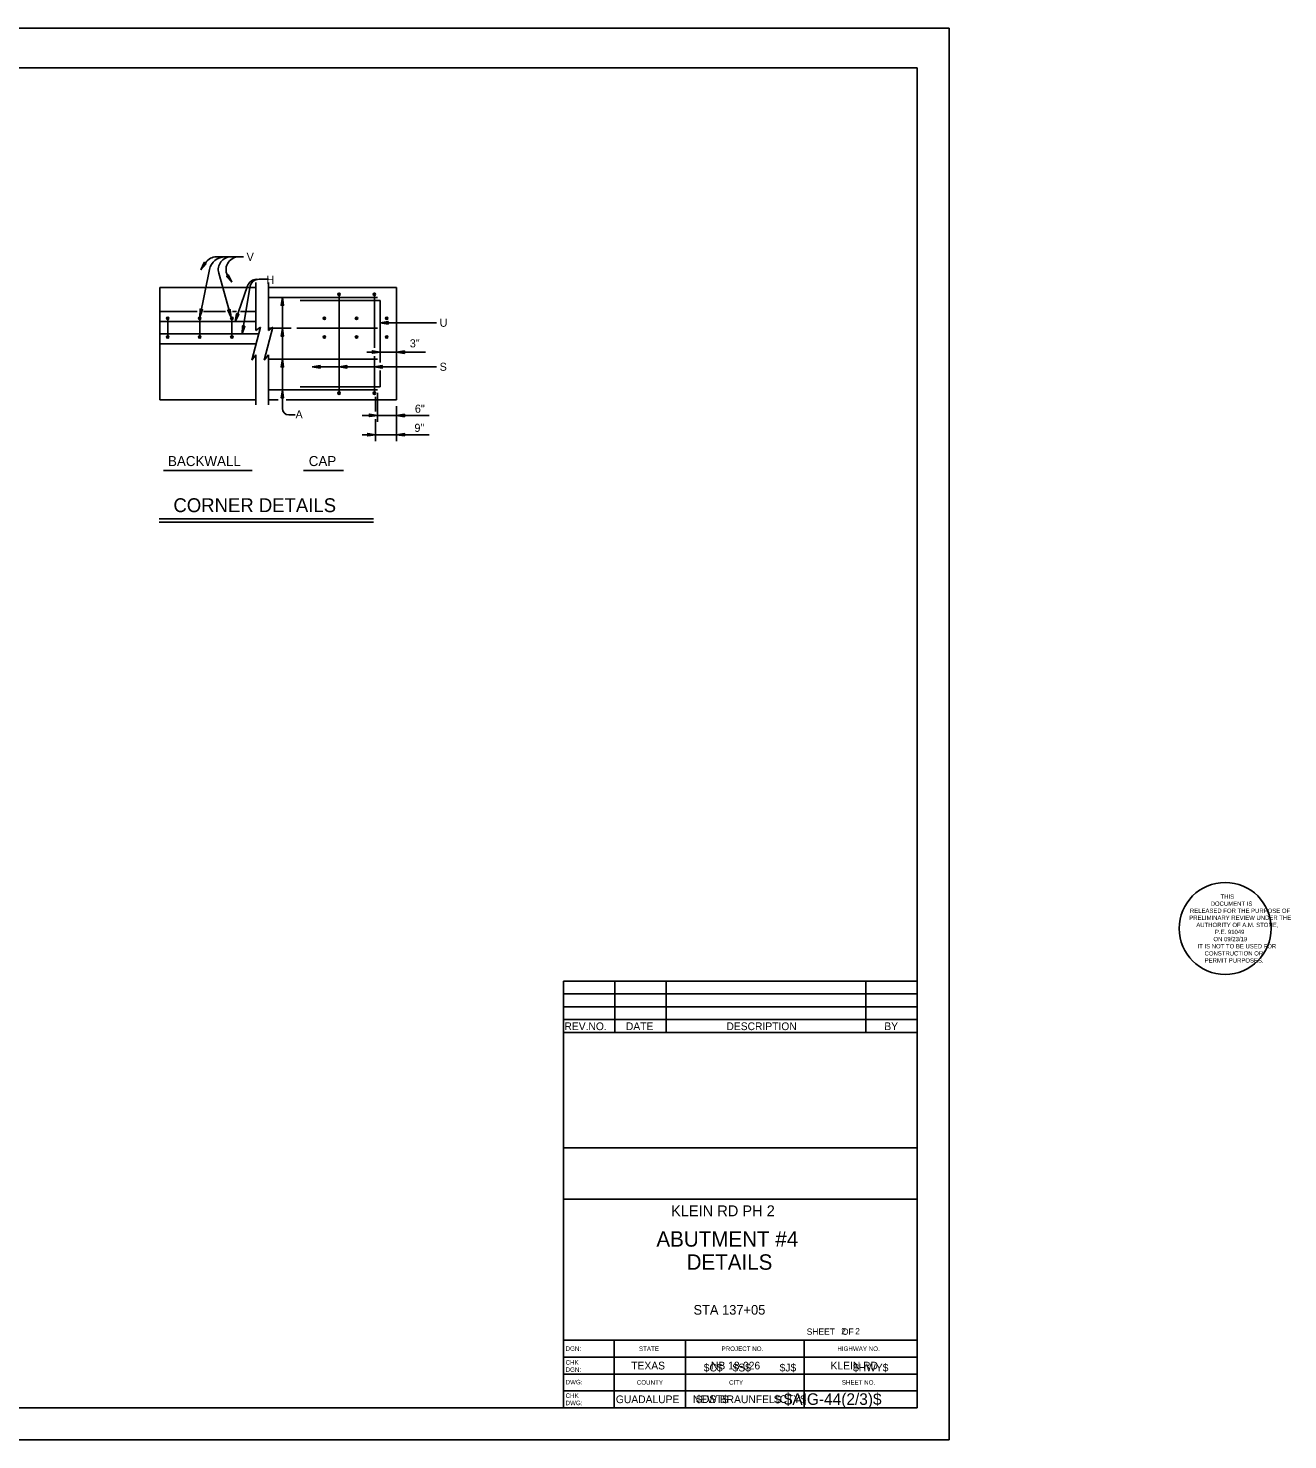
# Model space of a CAD drawing. Extents: x 926 to 1074, y 990 to 1081.
# Drawn here: x 1054.64 to 1074.28, y 1000 to 1022 of the extents above; entities that cross this region are included whole.
import ezdxf

# ---------------------------------------------------------------- set-up
doc = ezdxf.new("R2010")
doc.units = 0
for name, color, linetype in [('BORD_lines_major', 7, 'Continuous'), ('BORD_lines_minor', 7, 'Continuous'), ('BORD_text_large_1', 7, 'Continuous'), ('BORD_text_large_2', 7, 'Continuous'), ('BORD_text_small_1', 7, 'Continuous'), ('BORD_text_small_3', 7, 'Continuous'), ('BORD_text_small_proj', 7, 'Continuous'), ('C-MS-ANNO-TTLB-STMP', 7, 'Continuous'), ('D_BATCH_PLOT', 7, 'Continuous'), ('D_SHEET', 7, 'Continuous'), ('D_SHEET_NUM_CODE', 7, 'Continuous'), ('D_SHEET_TXT_SUB_CODE', 7, 'Continuous'), ('Working Level 1', 7, 'Continuous')]:
    doc.layers.add(name, color=color, linetype=linetype)

msp = doc.modelspace()

# ---------------------------------------------------------------- linework, layer by layer
at = {"layer": 'BORD_lines_major'}
for p, q in [((1037.413, 1021.382), (1068.5, 1021.382)), ((1068.5, 1000.5), (1068.5, 1021.382)), ((1037.413, 1000.5), (1068.5, 1000.5))]:
    msp.add_line(p, q, dxfattribs=at)
at = {"layer": 'BORD_lines_minor'}
for p, q in [((1062.988, 1007.15), (1068.5, 1007.15)), ((1062.988, 1006.35), (1062.988, 1007.15)), ((1062.988, 1006.95), (1068.5, 1006.95)), ((1063.788, 1007.15), (1063.788, 1006.35)), ((1064.588, 1007.15), (1064.588, 1006.35)), ((1067.7, 1006.35), (1067.7, 1007.15)), ((1062.988, 1006.75), (1068.5, 1006.75)), ((1062.988, 1006.55), (1068.5, 1006.55)), ((1062.988, 1006.35), (1068.5, 1006.35)), ((1062.988, 1006.35), (1062.988, 1004.55)), ((1062.988, 1004.55), (1068.5, 1004.55)), ((1062.988, 1004.55), (1062.988, 1000.5)), ((1062.988, 1003.75), (1068.5, 1003.75)), ((1062.988, 1001.55), (1068.5, 1001.55)), ((1063.776, 1001.55), (1063.776, 1000.5)), ((1064.888, 1001.55), (1064.888, 1000.5)), ((1066.738, 1001.55), (1066.738, 1000.5)), ((1062.988, 1001.287), (1068.5, 1001.287)), ((1062.988, 1001.025), (1068.5, 1001.025)), ((1062.988, 1000.762), (1068.5, 1000.762))]:
    msp.add_line(p, q, dxfattribs=at)
at = {"layer": 'C-MS-ANNO-TTLB-STMP'}
msp.add_circle((1073.305, 1007.969), 0.717, dxfattribs=at)
at = {"layer": 'D_BATCH_PLOT'}
msp.add_lwpolyline([(1035, 1000), (1069, 1000), (1069, 1022), (1035, 1022)], close=True, dxfattribs=at)
at = {"layer": 'D_SHEET'}
for p, q in [((1035, 1022), (1069, 1022)), ((1069, 1000), (1069, 1022)), ((1035, 1000), (1069, 1000))]:
    msp.add_line(p, q, dxfattribs=at)
at = {"layer": 'Working Level 1'}
for p, q in [((1057.574, 1018.437), (1057.995, 1018.437)), ((1057.315, 1017.498), (1057.466, 1018.237)), ((1057.33, 1018.236), (1057.409, 1018.35)), ((1057.611, 1018.184), (1057.803, 1017.492)), ((1056.692, 1016.208), (1056.692, 1017.958)), ((1058.192, 1017.958), (1056.692, 1017.958)), ((1057.818, 1018.041), (1057.761, 1018.124)), ((1057.867, 1017.429), (1058.062, 1017.987)), ((1057.979, 1017.237), (1058.094, 1017.961)), ((1058.192, 1017.288), (1058.192, 1018.036)), ((1058.388, 1018.087), (1058.242, 1018.087)), ((1058.385, 1017.288), (1058.385, 1018.036)), ((1058.385, 1017.958), (1060.385, 1017.958)), ((1060.385, 1016.208), (1060.385, 1017.958)), ((1058.385, 1017.804), (1060.085, 1017.804)), ((1058.604, 1016.074), (1058.604, 1017.804)), ((1058.881, 1017.754), (1060.131, 1017.754)), ((1059.487, 1017.854), (1059.487, 1016.312)), ((1060.039, 1017.854), (1060.039, 1017.018)), ((1060.131, 1017.754), (1060.131, 1016.789)), ((1057.276, 1017.583), (1056.692, 1017.583)), ((1057.718, 1017.583), (1057.374, 1017.583)), ((1057.891, 1017.583), (1057.826, 1017.583)), ((1058.192, 1017.583), (1057.949, 1017.583)), ((1058.192, 1017.429), (1056.692, 1017.429)), ((1056.817, 1017.187), (1056.817, 1017.479)), ((1057.317, 1017.187), (1057.317, 1017.479)), ((1057.817, 1017.187), (1057.817, 1017.479)), ((1058.126, 1016.827), (1058.264, 1017.34)), ((1058.264, 1017.34), (1058.192, 1017.288)), ((1058.319, 1016.827), (1058.457, 1017.34)), ((1058.457, 1017.34), (1058.385, 1017.288)), ((1058.385, 1017.324), (1058.435, 1017.324)), ((1058.453, 1017.324), (1058.74, 1017.324)), ((1058.829, 1017.324), (1060.085, 1017.324)), ((1060.131, 1017.41), (1061.009, 1017.41)), ((1058.237, 1017.237), (1056.692, 1017.237)), ((1058.195, 1017.083), (1056.692, 1017.083)), ((1058.192, 1016.907), (1058.126, 1016.827)), ((1058.192, 1016.13), (1058.192, 1016.907)), ((1058.385, 1016.907), (1058.319, 1016.827)), ((1058.385, 1016.13), (1058.385, 1016.907)), ((1058.385, 1016.843), (1060.085, 1016.843)), ((1060.835, 1016.952), (1059.92, 1016.952)), ((1060.039, 1016.89), (1060.039, 1016.312)), ((1059.068, 1016.724), (1061.009, 1016.724)), ((1060.131, 1016.665), (1060.131, 1016.412)), ((1058.881, 1016.412), (1060.131, 1016.412)), ((1058.192, 1016.208), (1056.692, 1016.208)), ((1058.385, 1016.362), (1060.085, 1016.362)), ((1058.385, 1016.208), (1058.539, 1016.208)), ((1058.663, 1016.208), (1060.385, 1016.208)), ((1060.058, 1016.253), (1060.058, 1016.026)), ((1060.085, 1016.315), (1060.085, 1015.865)), ((1058.704, 1015.974), (1058.803, 1015.974)), ((1060.892, 1015.965), (1059.848, 1015.965)), ((1060.385, 1016.108), (1060.385, 1015.565)), ((1060.058, 1015.909), (1060.058, 1015.565)), ((1060.892, 1015.665), (1059.848, 1015.665)), ((1056.751, 1015.108), (1058.135, 1015.108)), ((1058.933, 1015.108), (1059.555, 1015.108)), ((1056.681, 1014.353), (1060.025, 1014.353)), ((1056.681, 1014.303), (1060.025, 1014.303))]:
    msp.add_line(p, q, dxfattribs=at)
for points in [[(1057.33, 1018.236), (1057.383, 1018.349), (1057.415, 1018.327)], [(1057.818, 1018.041), (1057.765, 1018.153), (1057.733, 1018.131)], [(1058.604, 1017.804), (1058.584, 1017.682), (1058.623, 1017.682)], [(1057.315, 1017.498), (1057.359, 1017.614), (1057.321, 1017.622)], [(1057.803, 1017.492), (1057.79, 1017.616), (1057.752, 1017.605)], [(1057.867, 1017.429), (1057.926, 1017.538), (1057.89, 1017.551)], [(1057.979, 1017.237), (1058.018, 1017.355), (1057.98, 1017.361)], [(1058.604, 1017.324), (1058.584, 1017.201), (1058.623, 1017.201)], [(1060.131, 1017.41), (1060.253, 1017.39), (1060.253, 1017.428)], [(1058.604, 1016.843), (1058.584, 1016.72), (1058.623, 1016.72)], [(1060.131, 1016.952), (1060.008, 1016.972), (1060.008, 1016.934)], [(1060.385, 1016.952), (1060.507, 1016.932), (1060.507, 1016.971)], [(1059.068, 1016.724), (1059.191, 1016.704), (1059.191, 1016.742)], [(1059.487, 1016.724), (1059.609, 1016.704), (1059.609, 1016.742)], [(1060.039, 1016.724), (1060.162, 1016.704), (1060.162, 1016.742)], [(1058.604, 1016.362), (1058.584, 1016.24), (1058.623, 1016.24)], [(1060.085, 1015.965), (1059.962, 1015.985), (1059.962, 1015.946)], [(1060.385, 1015.965), (1060.507, 1015.945), (1060.507, 1015.984)], [(1060.058, 1015.665), (1059.935, 1015.685), (1059.935, 1015.646)], [(1060.385, 1015.665), (1060.507, 1015.645), (1060.507, 1015.684)]]:
    msp.add_lwpolyline(points, close=True, dxfattribs=at)
for centre, radius in [((1059.487, 1017.854), 0.0187), ((1059.487, 1017.854), 0.0117), ((1059.487, 1017.854), 0.00469), ((1060.039, 1017.854), 0.0187), ((1060.039, 1017.854), 0.0117), ((1060.039, 1017.854), 0.00469), ((1056.816, 1017.479), 0.0187), ((1056.816, 1017.479), 0.0117), ((1056.816, 1017.479), 0.00469), ((1057.316, 1017.479), 0.0187), ((1057.316, 1017.479), 0.0117), ((1057.316, 1017.479), 0.00469), ((1057.816, 1017.479), 0.0187), ((1057.816, 1017.479), 0.0117), ((1057.816, 1017.479), 0.00469), ((1059.26, 1017.479), 0.0187), ((1059.26, 1017.479), 0.0117), ((1059.26, 1017.479), 0.00469), ((1059.76, 1017.479), 0.0187), ((1059.76, 1017.479), 0.0117), ((1059.76, 1017.479), 0.00469), ((1060.231, 1017.479), 0.0187), ((1060.231, 1017.479), 0.0117), ((1060.231, 1017.479), 0.00469), ((1056.816, 1017.187), 0.0187), ((1056.816, 1017.187), 0.0117), ((1056.816, 1017.187), 0.00469), ((1057.316, 1017.187), 0.0187), ((1057.316, 1017.187), 0.0117), ((1057.316, 1017.187), 0.00469), ((1057.816, 1017.187), 0.0187), ((1057.816, 1017.187), 0.0117), ((1057.816, 1017.187), 0.00469), ((1059.26, 1017.187), 0.0187), ((1059.26, 1017.187), 0.0117), ((1059.26, 1017.187), 0.00469), ((1059.76, 1017.187), 0.0187), ((1059.76, 1017.187), 0.0117), ((1059.76, 1017.187), 0.00469), ((1060.231, 1017.187), 0.0187), ((1060.231, 1017.187), 0.0187), ((1060.231, 1017.187), 0.0117), ((1060.231, 1017.187), 0.0117), ((1060.231, 1017.187), 0.00469), ((1060.231, 1017.187), 0.00469), ((1059.487, 1016.312), 0.0187), ((1059.487, 1016.312), 0.0117), ((1059.487, 1016.312), 0.00469), ((1060.039, 1016.312), 0.0187), ((1060.039, 1016.312), 0.0117), ((1060.039, 1016.312), 0.00469)]:
    msp.add_circle(centre, radius, dxfattribs=at)
for centre, radius, start, end in [((1057.574, 1018.237), 0.2, 90, 145.4917), ((1057.711, 1018.187), 0.25, 90, 168.4552), ((1057.804, 1018.237), 0.2, 90, 195.5006), ((1057.925, 1018.237), 0.2, 90, 214.524), ((1058.203, 1017.937), 0.15, 90, 160.7438), ((1058.242, 1017.937), 0.15, 90, 170.9957), ((1058.704, 1016.074), 0.1, 180, 270)]:
    msp.add_arc(centre, radius, start, end, dxfattribs=at)

# ---------------------------------------------------------------- texts
at = {"layer": 'BORD_lines_minor'}
for s, p in [('REV.NO.', (1063.002, 1006.385)), ('DATE', (1063.96, 1006.385)), ('DESCRIPTION', (1065.528, 1006.385)), ('BY', (1067.99, 1006.385))]:
    msp.add_text(s, height=0.12, rotation=359.9834, dxfattribs=at).set_placement(p)
msp.add_text('KLEIN RD PH 2', height=0.17, dxfattribs=at).set_placement((1064.665, 1003.483))
at = {"layer": 'BORD_text_large_1'}
for s, p in [('ABUTMENT #4', (1064.436, 1003.01)), ('DETAILS', (1064.907, 1002.65))]:
    msp.add_text(s, height=0.24, dxfattribs=at).set_placement(p)
at = {"layer": 'BORD_text_large_2'}
msp.add_text('STA 137+05', height=0.15, dxfattribs=at).set_placement((1065.014, 1001.95))
at = {"layer": 'BORD_text_small_1'}
msp.add_text('SHEET   OF', height=0.0984, dxfattribs=at).set_placement((1066.78, 1001.636))
at = {"layer": 'BORD_text_small_3'}
msp.add_text('2    2', height=0.0984, dxfattribs=at).set_placement((1067.316, 1001.642))
at = {"layer": 'BORD_text_small_proj'}
for s, height, p in [('DGN:', 0.07, (1063.02, 1001.386)), ('STATE', 0.07, (1064.164, 1001.384)), ('PROJECT NO.', 0.07, (1065.452, 1001.384)), ('HIGHWAY NO.', 0.07, (1067.258, 1001.384)), ('CHK', 0.07, (1063.02, 1001.171)), ('DGN:', 0.07, (1063.02, 1001.058)), ('TEXAS', 0.12, (1064.044, 1001.096)), ('KLEIN RD', 0.12, (1067.151, 1001.096)), ('DWG:', 0.07, (1063.02, 1000.864)), ('COUNTY', 0.07, (1064.13, 1000.859)), ('CITY', 0.07, (1065.569, 1000.859)), ('SHEET NO.', 0.07, (1067.327, 1000.859)), ('CHK', 0.07, (1063.02, 1000.653)), ('DWG:', 0.07, (1063.02, 1000.539)), ('GUADALUPE', 0.12, (1063.804, 1000.571)), ('NEW BRAUNFELS', 0.12, (1065.005, 1000.571))]:
    msp.add_text(s, height=height, rotation=359.9834, dxfattribs=at).set_placement(p)
msp.add_text('NB 18-026', height=0.12, dxfattribs=at).set_placement((1065.287, 1001.096))
at = {"layer": 'C-MS-ANNO-TTLB-STMP'}
for s, height, p in [('THIS', 0.0672, (1073.233, 1008.433)), ('RELEASED FOR THE PURPOSE OF', 0.06723, (1072.755, 1008.211)), ('DOCUMENT IS', 0.06723, (1073.079, 1008.322)), ('PRELIMINARY REVIEW UNDER THE', 0.06723, (1072.746, 1008.102)), ('AUTHORITY OF A.M. STONE,', 0.06723, (1072.855, 1007.991)), ('ON 09/23/19', 0.06723, (1073.122, 1007.77)), ('P.E. 91049', 0.0672, (1073.146, 1007.881)), ('IT IS NOT TO BE USED FOR', 0.06723, (1072.874, 1007.659)), ('CONSTRUCTION OR', 0.06723, (1072.984, 1007.548)), ('PERMIT PURPOSES.', 0.06723, (1072.985, 1007.437))]:
    msp.add_text(s, height=height, rotation=360, dxfattribs=at).set_placement(p)
at = {"layer": 'D_SHEET_NUM_CODE'}
msp.add_text('$AIG-44(2/3)$', height=0.18, dxfattribs=at).set_placement((1066.422, 1000.544))
at = {"layer": 'D_SHEET_TXT_SUB_CODE'}
for s, p in [('$C$', (1065.174, 1001.065)), ('$S$', (1065.624, 1001.065)), ('$J$', (1066.357, 1001.065)), ('$HWY$', (1067.501, 1001.065)), ('$DST$', (1065.055, 1000.574)), ('$CTY$', (1066.27, 1000.574))]:
    msp.add_text(s, height=0.12, dxfattribs=at).set_placement(p)
at = {"layer": 'Working Level 1'}
for s, height, p in [('V', 0.126, (1058.046, 1018.374)), (' H', 0.126, (1058.309, 1018.015)), (' U', 0.126, (1061.009, 1017.347)), ('3"', 0.126, (1060.591, 1017.026)), (' S', 0.126, (1061.009, 1016.661)), (' A', 0.126, (1058.762, 1015.918)), ('6"', 0.126, (1060.67, 1016.007)), ('9"', 0.126, (1060.663, 1015.709)), ('BACKWALL', 0.156, (1056.82, 1015.176)), ('CAP', 0.156, (1059.015, 1015.176)), ('CORNER DETAILS', 0.216, (1056.905, 1014.458))]:
    msp.add_text(s, height=height, dxfattribs=at).set_placement(p)

doc.saveas('drawing.dxf')
